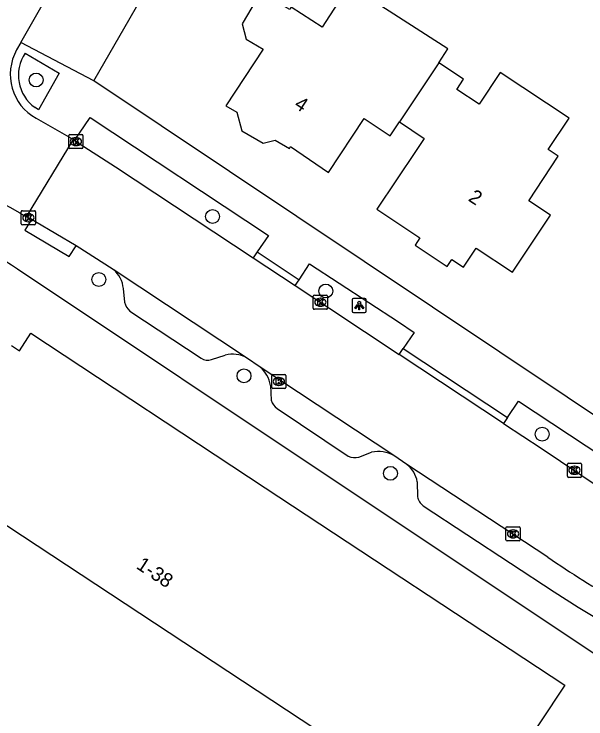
# Model space of a CAD drawing. Extents: x 161772 to 163123, y 383092 to 383917.
# Drawn here: x 162369.56 to 162409.94, y 383483.68 to 383533.43 of the extents above; entities that cross this region are included whole.
import ezdxf

# ---------------------------------------------------------------- set-up
doc = ezdxf.new("R2010")
doc.units = 0
for name, color, linetype in [('IMGEO_Boom', 7, 'Continuous'), ('IMGEO_Kolk', 7, 'Continuous'), ('IMGEO_Lichtpunt', 7, 'Continuous'), ('IMGEO_Pand', 7, 'Continuous'), ('IMGEO_Pand_nummerreeks', 7, 'Continuous'), ('IMGEO_Rijbaan_lokaal_gesloten', 7, 'Continuous'), ('IMGEO_Rijbaan_lokaal_open', 7, 'Continuous'), ('IMGEO_Voetpad_open', 7, 'Continuous')]:
    doc.layers.add(name, color=color, linetype=linetype)

msp = doc.modelspace()

# ---------------------------------------------------------------- linework, layer by layer
at = {"layer": 'IMGEO_Boom'}
for centre in [(162371.117, 383528.782), (162383.578, 383519.145), (162375.545, 383514.701), (162391.571, 383513.885), (162385.797, 383507.897), (162406.85, 383503.782), (162396.136, 383501.014)]:
    msp.add_circle(centre, 0.489, dxfattribs=at)
at = {"layer": 'IMGEO_Kolk'}
for p, q in [((162373.427, 383524.01), (162373.427, 383524.862)), ((162373.502, 383524.936), (162374.354, 383524.936)), ((162373.915, 383524.716), (162373.94, 383524.716)), ((162374.428, 383524.862), (162374.428, 383524.01)), ((162373.938, 383524.156), (162373.913, 383524.156)), ((162374.354, 383523.936), (162373.502, 383523.936)), ((162370.072, 383518.63), (162370.072, 383519.482)), ((162370.147, 383519.556), (162370.999, 383519.556)), ((162370.56, 383519.336), (162370.585, 383519.336)), ((162371.073, 383519.482), (162371.073, 383518.63)), ((162370.583, 383518.776), (162370.558, 383518.776)), ((162370.999, 383518.556), (162370.147, 383518.556)), ((162390.69, 383512.667), (162390.69, 383513.519)), ((162390.765, 383513.593), (162391.617, 383513.593)), ((162391.178, 383513.373), (162391.203, 383513.373)), ((162391.691, 383513.519), (162391.691, 383512.667)), ((162391.201, 383512.813), (162391.176, 383512.813)), ((162391.617, 383512.593), (162390.765, 383512.593)), ((162387.758, 383507.072), (162387.758, 383507.924)), ((162387.833, 383507.998), (162388.685, 383507.998)), ((162388.246, 383507.778), (162388.271, 383507.778)), ((162388.759, 383507.924), (162388.759, 383507.072)), ((162388.685, 383506.998), (162387.833, 383506.998)), ((162388.269, 383507.218), (162388.244, 383507.218)), ((162408.633, 383500.804), (162408.633, 383501.656)), ((162408.708, 383501.73), (162409.56, 383501.73)), ((162409.121, 383501.51), (162409.146, 383501.51)), ((162409.634, 383501.656), (162409.634, 383500.804)), ((162409.144, 383500.95), (162409.119, 383500.95)), ((162409.56, 383500.73), (162408.708, 383500.73)), ((162404.297, 383496.315), (162404.297, 383497.167)), ((162404.372, 383497.241), (162405.224, 383497.241)), ((162404.785, 383497.021), (162404.81, 383497.021)), ((162405.298, 383497.167), (162405.298, 383496.315)), ((162404.808, 383496.461), (162404.783, 383496.461)), ((162405.224, 383496.241), (162404.372, 383496.241))]:
    msp.add_line(p, q, dxfattribs=at)
for points in [[(162373.427, 383524.01), (162373.427, 383524.862)], [(162373.502, 383524.936), (162374.354, 383524.936)], [(162374.428, 383524.862), (162374.428, 383524.01)], [(162373.748, 383524.636), (162373.871, 383524.636), (162373.871, 383524.485), (162374.001, 383524.636), (162374.165, 383524.636), (162374.019, 383524.485), (162374.172, 383524.236), (162374.02, 383524.236), (162373.935, 383524.4), (162373.871, 383524.333), (162373.871, 383524.236), (162373.748, 383524.236), (162373.748, 383524.636)], [(162374.354, 383523.936), (162373.502, 383523.936)], [(162370.072, 383518.63), (162370.072, 383519.482)], [(162370.147, 383519.556), (162370.999, 383519.556)], [(162370.393, 383519.256), (162370.516, 383519.256), (162370.516, 383519.105), (162370.646, 383519.256), (162370.81, 383519.256), (162370.664, 383519.105), (162370.817, 383518.856), (162370.665, 383518.856), (162370.58, 383519.02), (162370.516, 383518.953), (162370.516, 383518.856), (162370.393, 383518.856), (162370.393, 383519.256)], [(162371.073, 383519.482), (162371.073, 383518.63)], [(162370.999, 383518.556), (162370.147, 383518.556)], [(162390.69, 383512.667), (162390.69, 383513.519)], [(162390.765, 383513.593), (162391.617, 383513.593)], [(162391.011, 383513.293), (162391.134, 383513.293), (162391.134, 383513.142), (162391.264, 383513.293), (162391.428, 383513.293), (162391.282, 383513.142), (162391.435, 383512.893), (162391.283, 383512.893), (162391.198, 383513.057), (162391.134, 383512.99), (162391.134, 383512.893), (162391.011, 383512.893), (162391.011, 383513.293)], [(162391.691, 383513.519), (162391.691, 383512.667)], [(162391.617, 383512.593), (162390.765, 383512.593)], [(162387.758, 383507.072), (162387.758, 383507.924)], [(162387.833, 383507.998), (162388.685, 383507.998)], [(162388.759, 383507.924), (162388.759, 383507.072)], [(162388.079, 383507.698), (162388.202, 383507.698), (162388.202, 383507.547), (162388.332, 383507.698), (162388.496, 383507.698), (162388.35, 383507.547), (162388.503, 383507.298), (162388.351, 383507.298), (162388.266, 383507.462), (162388.202, 383507.395), (162388.202, 383507.298), (162388.079, 383507.298), (162388.079, 383507.698)], [(162388.685, 383506.998), (162387.833, 383506.998)], [(162408.633, 383500.804), (162408.633, 383501.656)], [(162408.708, 383501.73), (162409.56, 383501.73)], [(162408.954, 383501.43), (162409.077, 383501.43), (162409.077, 383501.279), (162409.207, 383501.43), (162409.371, 383501.43), (162409.225, 383501.279), (162409.378, 383501.03), (162409.226, 383501.03), (162409.141, 383501.194), (162409.077, 383501.127), (162409.077, 383501.03), (162408.954, 383501.03), (162408.954, 383501.43)], [(162409.634, 383501.656), (162409.634, 383500.804)], [(162409.56, 383500.73), (162408.708, 383500.73)], [(162404.297, 383496.315), (162404.297, 383497.167)], [(162404.372, 383497.241), (162405.224, 383497.241)], [(162404.618, 383496.941), (162404.741, 383496.941), (162404.741, 383496.79), (162404.871, 383496.941), (162405.035, 383496.941), (162404.889, 383496.79), (162405.042, 383496.541), (162404.89, 383496.541), (162404.805, 383496.705), (162404.741, 383496.638), (162404.741, 383496.541), (162404.618, 383496.541), (162404.618, 383496.941)], [(162405.298, 383497.167), (162405.298, 383496.315)], [(162405.224, 383496.241), (162404.372, 383496.241)]]:
    msp.add_lwpolyline(points, dxfattribs=at)
for centre, start, end in [((162373.504, 383524.86), 91.552, 178.448), ((162373.504, 383524.86), 91.552, 178.448), ((162374.352, 383524.86), 1.552, 88.448), ((162374.352, 383524.86), 1.552, 88.448), ((162373.504, 383524.012), 181.552, 268.448), ((162373.504, 383524.012), 181.552, 268.448), ((162374.352, 383524.012), 271.552, 358.448), ((162374.352, 383524.012), 271.552, 358.448), ((162370.149, 383519.48), 91.552, 178.448), ((162370.149, 383519.48), 91.552, 178.448), ((162370.997, 383519.48), 1.552, 88.448), ((162370.997, 383519.48), 1.552, 88.448), ((162370.149, 383518.632), 181.552, 268.448), ((162370.149, 383518.632), 181.552, 268.448), ((162370.997, 383518.632), 271.552, 358.448), ((162370.997, 383518.632), 271.552, 358.448), ((162390.767, 383513.517), 91.552, 178.448), ((162390.767, 383513.517), 91.552, 178.448), ((162391.615, 383513.517), 1.552, 88.448), ((162391.615, 383513.517), 1.552, 88.448), ((162390.767, 383512.669), 181.552, 268.448), ((162390.767, 383512.669), 181.552, 268.448), ((162391.615, 383512.669), 271.552, 358.448), ((162391.615, 383512.669), 271.552, 358.448), ((162387.835, 383507.922), 91.552, 178.448), ((162387.835, 383507.922), 91.552, 178.448), ((162388.683, 383507.922), 1.552, 88.448), ((162388.683, 383507.922), 1.552, 88.448), ((162387.835, 383507.074), 181.552, 268.448), ((162387.835, 383507.074), 181.552, 268.448), ((162388.683, 383507.074), 271.552, 358.448), ((162388.683, 383507.074), 271.552, 358.448), ((162408.71, 383501.654), 91.552, 178.448), ((162408.71, 383501.654), 91.552, 178.448), ((162409.558, 383501.654), 1.552, 88.448), ((162409.558, 383501.654), 1.552, 88.448), ((162408.71, 383500.806), 181.552, 268.448), ((162408.71, 383500.806), 181.552, 268.448), ((162409.558, 383500.806), 271.552, 358.448), ((162409.558, 383500.806), 271.552, 358.448), ((162404.374, 383497.165), 91.552, 178.448), ((162404.374, 383497.165), 91.552, 178.448), ((162405.222, 383497.165), 1.552, 88.448), ((162405.222, 383497.165), 1.552, 88.448), ((162404.374, 383496.317), 181.552, 268.448), ((162404.374, 383496.317), 181.552, 268.448), ((162405.222, 383496.317), 271.552, 358.448), ((162405.222, 383496.317), 271.552, 358.448)]:
    msp.add_arc(centre, 0.0765, start, end, dxfattribs=at)
for centre, major_axis, ratio, start_param, end_param in [((162373.914, 383524.436), (-0.387, 0.002), 0.722429, 4.712389, 7.853982), ((162373.939, 383524.436), (-0.39, 0.002), 0.717154, 1.570796, 4.712389), ((162370.559, 383519.056), (-0.387, 0.002), 0.722429, 4.712389, 7.853982), ((162370.584, 383519.056), (-0.39, 0.002), 0.717154, 1.570796, 4.712389), ((162391.177, 383513.093), (-0.387, 0.002), 0.722429, 4.712389, 7.853982), ((162391.202, 383513.093), (-0.39, 0.002), 0.717154, 1.570796, 4.712389), ((162388.245, 383507.498), (-0.387, 0.002), 0.722429, 4.712389, 7.853982), ((162388.27, 383507.498), (-0.39, 0.002), 0.717154, 1.570796, 4.712389), ((162409.12, 383501.23), (-0.387, 0.002), 0.722429, 4.712389, 7.853982), ((162409.145, 383501.23), (-0.39, 0.002), 0.717154, 1.570796, 4.712389), ((162404.784, 383496.741), (-0.387, 0.002), 0.722429, 4.712389, 7.853982), ((162404.809, 383496.741), (-0.39, 0.002), 0.717154, 1.570796, 4.712389)]:
    msp.add_ellipse(centre, major_axis=major_axis, ratio=ratio, start_param=start_param, end_param=end_param, dxfattribs=at)
at = {"layer": 'IMGEO_Lichtpunt'}
for p, q in [((162393.439, 383513.262), (162393.439, 383512.455)), ((162393.439, 383513.262), (162393.439, 383512.455)), ((162394.341, 383513.357), (162393.533, 383513.357)), ((162394.341, 383513.357), (162393.533, 383513.357)), ((162394.435, 383512.455), (162394.435, 383513.262)), ((162394.435, 383512.455), (162394.435, 383513.262)), ((162393.533, 383512.361), (162394.341, 383512.361)), ((162393.533, 383512.361), (162394.341, 383512.361))]:
    msp.add_line(p, q, dxfattribs=at)
for points in [[(162393.813, 383512.926), (162393.852, 383512.898), (162393.664, 383512.636), (162393.626, 383512.663), (162393.813, 383512.926)], [(162393.915, 383512.878), (162393.962, 383512.878), (162393.962, 383512.556), (162393.915, 383512.556), (162393.915, 383512.878)], [(162394.025, 383512.898), (162394.063, 383512.925), (162394.25, 383512.663), (162394.211, 383512.635), (162394.025, 383512.898)]]:
    msp.add_lwpolyline(points, dxfattribs=at)
msp.add_circle((162393.938, 383513.06), 0.0994, dxfattribs=at)
for centre, start, end in [((162393.533, 383513.262), 90, 180), ((162393.533, 383513.262), 90, 180), ((162394.341, 383513.262), 0, 90), ((162394.341, 383513.262), 0, 90), ((162393.533, 383512.455), 180, 270), ((162393.533, 383512.455), 180, 270), ((162394.341, 383512.455), 270, 0), ((162394.341, 383512.455), 270, 360)]:
    msp.add_arc(centre, 0.0946, start, end, dxfattribs=at)
at = {"layer": 'IMGEO_Pand'}
for points in [[(162399.551, 383529.998), (162400.202, 383530.976), (162393.215, 383535.465), (162391.317, 383532.512), (162389.13, 383533.918), (162389.026, 383533.768), (162387.838, 383534.453), (162386.648, 383534.452), (162385.666, 383532.751), (162385.959, 383531.659), (162387.161, 383530.966), (162384.511, 383526.964), (162385.295, 383526.511), (162385.651, 383525.187), (162387.16, 383524.317), (162387.994, 383524.54), (162389.009, 383523.954), (162389.089, 383524.092), (162391.754, 383522.254), (162394.289, 383526.056), (162396.111, 383524.841), (162396.772, 383525.831)], [(162396.772, 383525.831), (162398.523, 383524.663), (162397.959, 383523.815), (162395.189, 383519.652), (162398.22, 383517.636), (162397.885, 383517.133), (162400.148, 383515.627), (162400.476, 383516.119), (162401.305, 383515.567), (162402.195, 383516.905), (162404.746, 383515.207), (162407.433, 383519.245), (162405.908, 383520.26), (162407.993, 383523.394), (162407.282, 383523.868), (162408.758, 383526.086), (162403.897, 383529.321), (162402.399, 383527.07), (162400.823, 383528.119), (162401.299, 383528.834), (162399.551, 383529.998)], [(162399.551, 383529.998), (162396.772, 383525.831)], [(162369.386, 383510.049), (162369.936, 383509.674), (162370.747, 383510.9), (162387.282, 383500), (162408.441, 383486.052), (162399.683, 383472.842), (162389.098, 383463.766), (162387.275, 383465.894), (162382.993, 383470.891), (162381.153, 383473.039), (162391.903, 383482.254), (162364.962, 383500), (162363.969, 383500.654), (162365.459, 383502.906), (162364.939, 383503.25)]]:
    msp.add_lwpolyline(points, dxfattribs=at)
at = {"layer": 'IMGEO_Rijbaan_lokaal_gesloten'}
for points in [[(162373.747, 383524.572), (162373.834, 383524.516)], [(162373.834, 383524.516), (162376.728, 383522.659), (162386.44, 383516.235)], [(162370.793, 383518.936), (162370.441, 383519.129)], [(162373.944, 383517.081), (162371.077, 383518.78), (162370.793, 383518.936)], [(162376.564, 383515.408), (162373.944, 383517.081)], [(162386.44, 383516.235), (162389.421, 383514.263)], [(162385.982, 383509.168), (162376.564, 383515.408)], [(162389.421, 383514.263), (162396.76, 383509.409)], [(162404.125, 383504.54), (162396.76, 383509.409)], [(162386.933, 383508.51), (162385.982, 383509.168)], [(162396.376, 383502.271), (162386.933, 383508.51)], [(162404.125, 383504.54), (162404.195, 383504.494), (162406.79, 383502.794), (162410.958, 383500), (162415.501, 383497.08)], [(162397.286, 383501.636), (162396.376, 383502.271)], [(162407.244, 383495.103), (162397.286, 383501.636)]]:
    msp.add_lwpolyline(points, dxfattribs=at)
msp.add_arc((162441.367, 383544.326), 59.894, 235.26876, 240.96925, dxfattribs=at)
at = {"layer": 'IMGEO_Rijbaan_lokaal_open'}
for points in [[(162370.031, 383531.42), (162372.207, 383535.252)], [(162370.031, 383531.42), (162369.74, 383530.907)], [(162371.119, 383526.076), (162373.747, 383524.572)], [(162370.441, 383519.129), (162373.747, 383524.572)], [(162369.997, 383519.372), (162370.441, 383519.129)]]:
    msp.add_lwpolyline(points, dxfattribs=at)
for centre, radius, start, end in [((162372.859, 383529.185), 3.563, 151.0941, 240.7684), ((162356.098, 383495.402), 27.708, 59.8918, 86.7549)]:
    msp.add_arc(centre, radius, start, end, dxfattribs=at)
at = {"layer": 'IMGEO_Voetpad_open'}
for points in [[(162375.184, 383528.714), (162442.25, 383644.984)], [(162375.184, 383528.714), (162370.031, 383531.42)], [(162370.342, 383530.686), (162372.745, 383529.264), (162371.276, 383526.684)], [(162425.357, 383495.215), (162418.191, 383500), (162375.184, 383528.714)], [(162371.276, 383526.684), (162371.048, 383526.834)], [(162373.834, 383524.516), (162374.942, 383526.139), (162387.516, 383517.815), (162386.721, 383516.648)], [(162370.793, 383518.936), (162370.313, 383518.185), (162373.448, 383516.33), (162373.944, 383517.081)], [(162386.721, 383516.648), (162386.44, 383516.235)], [(162386.721, 383516.648), (162389.694, 383514.682)], [(162389.694, 383514.682), (162390.42, 383515.798), (162396.699, 383511.708), (162397.802, 383510.956), (162397.037, 383509.82)], [(162415.606, 383482.867), (162415.154, 383485.181), (162392.934, 383500), (162369.796, 383515.431)], [(162389.421, 383514.263), (162389.694, 383514.682)], [(162377.276, 383514.059), (162377.368, 383513.091)], [(162377.742, 383512.469), (162382.771, 383509.14)], [(162396.76, 383509.409), (162397.037, 383509.82)], [(162397.037, 383509.82), (162404.404, 383504.955)], [(162383.497, 383509.057), (162384.479, 383509.356)], [(162387.662, 383507.225), (162387.706, 383506.17)], [(162404.404, 383504.955), (162405.174, 383506.099), (162417.08, 383498.245), (162419.246, 383496.818), (162418.384, 383495.476)], [(162388.148, 383505.586), (162393.153, 383502.222)], [(162404.404, 383504.955), (162404.125, 383504.54)], [(162393.908, 383502.163), (162394.812, 383502.507)], [(162398.024, 383500.411), (162398.038, 383499.365)], [(162398.456, 383498.732), (162407.701, 383492.642), (162409.387, 383491.566), (162410.568, 383490.866)]]:
    msp.add_lwpolyline(points, dxfattribs=at)
for centre, radius, start, end in [((162372.668, 383529.122), 2.803, 146.0696, 234.7023), ((162355.644, 383494.899), 24.937, 55.4234, 93.0188), ((162375.378, 383513.919), 1.904, 4.205, 51.445), ((162378.377, 383513.274), 1.025, 190.2892, 231.7467), ((162385.009, 383507.493), 1.937, 59.8483, 105.8923), ((162383.211, 383509.773), 0.771, 235.1982, 291.7578), ((162385.674, 383506.946), 2.008, 7.9775, 51.1563), ((162388.947, 383506.65), 1.33, 201.1405, 233.0999), ((162395.285, 383500.338), 2.22, 60.5459, 102.2922), ((162393.625, 383503.408), 1.277, 248.2784, 282.7849), ((162396.278, 383500.194), 1.759, 7.0866, 55.047), ((162399.129, 383499.631), 1.123, 193.6931, 233.1842)]:
    msp.add_arc(centre, radius, start, end, dxfattribs=at)

# ---------------------------------------------------------------- texts
at = {"layer": 'IMGEO_Pand_nummerreeks'}
for s, rotation, p in [('4', 326.9647, (162389.278, 383526.87)), ('2', 326.7687, (162401.572, 383520.299)), ('1-38', 326.6273, (162378.123, 383494.348))]:
    msp.add_text(s, height=1, rotation=rotation, dxfattribs=at).set_placement(p)

doc.saveas('drawing.dxf')
